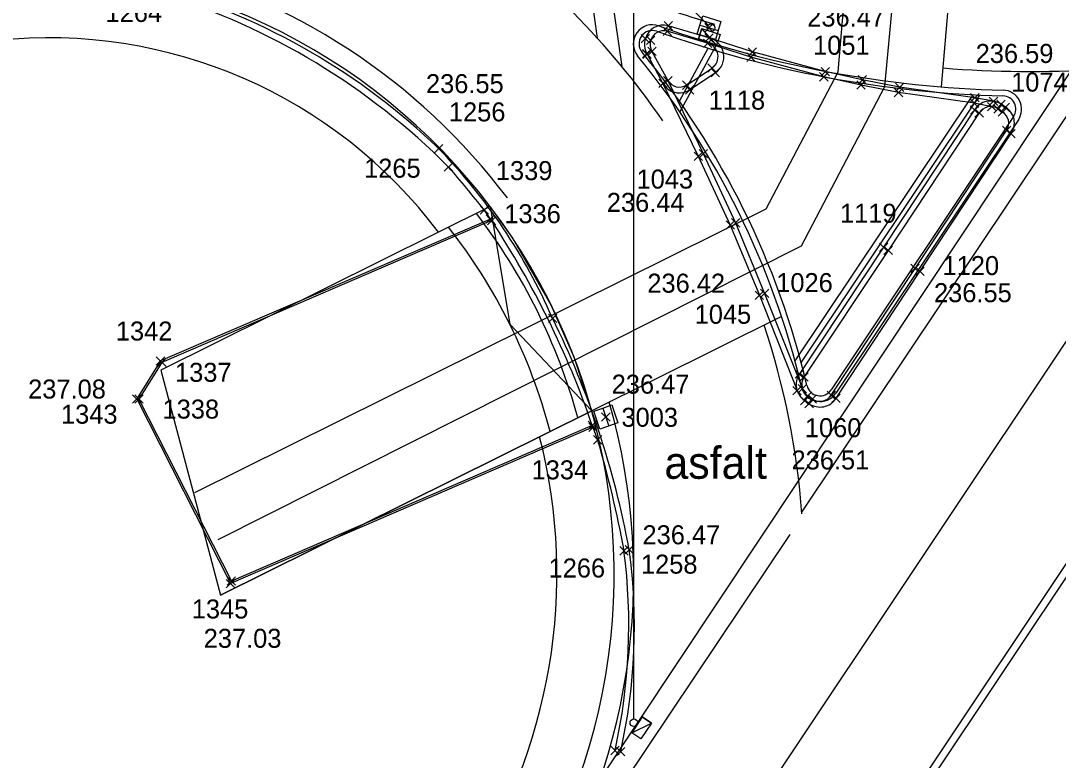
# Model space of a CAD drawing. Extents: x -264205 to -263615, y -1242401 to -1242031.
# Drawn here: x -263835.79 to -263808.5, y -1242333.91 to -1242314.46 of the extents above; entities that cross this region are included whole.
import ezdxf

# ---------------------------------------------------------------- set-up
doc = ezdxf.new("R2010")
doc.units = 0
for name, color, linetype in [('BODY_SYMBOL A CISLO_2-1', 7, 'Continuous'), ('BODY_VYSKA_2-1', 7, 'Continuous'), ('KOORDINACNA_SITUACIA_DSP', 7, 'Continuous'), ('POPIS', 7, 'Continuous'), ('PROJEKT_DRS_TDZ_VODOROVNE', 7, 'Continuous'), ('SO_20-1_OBRUBNIKY_DOLNA_HRANA', 7, 'Continuous'), ('SO_20-1_OBRUBNIKY_HORNA_HRANA', 7, 'Continuous'), ('SO_20-1_UV', 7, 'Continuous')]:
    doc.layers.add(name, color=color, linetype=linetype)

msp = doc.modelspace()

# ---------------------------------------------------------------- linework, layer by layer
at = {"layer": 'BODY_SYMBOL A CISLO_2-1'}
for p, q in [((-263818.899, -1242314.846), (-263818.678, -1242314.626)), ((-263818.678, -1242314.846), (-263818.899, -1242314.626)), ((-263818.872, -1242314.704), (-263818.65, -1242314.484)), ((-263818.65, -1242314.704), (-263818.872, -1242314.484)), ((-263817.799, -1242314.757), (-263817.578, -1242314.535)), ((-263817.578, -1242314.757), (-263817.799, -1242314.535)), ((-263819.474, -1242315.039), (-263819.253, -1242314.819)), ((-263819.253, -1242315.039), (-263819.474, -1242314.819)), ((-263819.335, -1242315.086), (-263819.114, -1242314.865)), ((-263819.114, -1242315.086), (-263819.335, -1242314.865)), ((-263817.801, -1242315.024), (-263817.579, -1242314.802)), ((-263817.579, -1242315.024), (-263817.801, -1242314.802)), ((-263819.302, -1242315.377), (-263819.081, -1242315.157)), ((-263819.081, -1242315.377), (-263819.302, -1242315.157)), ((-263817.838, -1242315.161), (-263817.617, -1242314.941)), ((-263817.617, -1242315.161), (-263817.838, -1242314.941)), ((-263816.658, -1242315.39), (-263816.437, -1242315.17)), ((-263816.437, -1242315.39), (-263816.658, -1242315.17)), ((-263819.44, -1242315.434), (-263819.219, -1242315.214)), ((-263819.219, -1242315.434), (-263819.44, -1242315.214)), ((-263819.43, -1242315.451), (-263819.209, -1242315.231)), ((-263819.209, -1242315.451), (-263819.43, -1242315.231)), ((-263816.696, -1242315.529), (-263816.475, -1242315.308)), ((-263816.475, -1242315.529), (-263816.696, -1242315.308)), ((-263817.719, -1242315.815), (-263817.497, -1242315.593)), ((-263817.497, -1242315.815), (-263817.719, -1242315.593)), ((-263817.636, -1242315.938), (-263817.415, -1242315.718)), ((-263817.415, -1242315.938), (-263817.636, -1242315.718)), ((-263814.743, -1242315.909), (-263814.522, -1242315.688)), ((-263814.522, -1242315.909), (-263814.743, -1242315.688)), ((-263819.013, -1242316.218), (-263818.791, -1242315.998)), ((-263818.791, -1242316.218), (-263819.013, -1242315.998)), ((-263818.883, -1242316.146), (-263818.662, -1242315.924)), ((-263818.662, -1242316.146), (-263818.883, -1242315.924)), ((-263814.78, -1242316.046), (-263814.558, -1242315.825)), ((-263814.558, -1242316.046), (-263814.78, -1242315.825)), ((-263813.77, -1242316.126), (-263813.549, -1242315.904)), ((-263813.549, -1242316.126), (-263813.77, -1242315.904)), ((-263818.391, -1242316.265), (-263818.17, -1242316.043)), ((-263818.17, -1242316.265), (-263818.391, -1242316.043)), ((-263818.312, -1242316.389), (-263818.09, -1242316.167)), ((-263818.09, -1242316.389), (-263818.312, -1242316.167)), ((-263813.8, -1242316.262), (-263813.579, -1242316.042)), ((-263813.579, -1242316.262), (-263813.8, -1242316.042)), ((-263812.815, -1242316.46), (-263812.594, -1242316.238)), ((-263812.594, -1242316.46), (-263812.815, -1242316.238)), ((-263812.788, -1242316.32), (-263812.567, -1242316.1)), ((-263812.567, -1242316.32), (-263812.788, -1242316.1)), ((-263810.819, -1242316.738), (-263810.598, -1242316.518)), ((-263810.598, -1242316.738), (-263810.819, -1242316.518)), ((-263810.808, -1242316.596), (-263810.587, -1242316.374)), ((-263810.587, -1242316.596), (-263810.808, -1242316.374)), ((-263810.317, -1242316.688), (-263810.095, -1242316.468)), ((-263810.095, -1242316.688), (-263810.317, -1242316.468)), ((-263810.815, -1242316.917), (-263810.594, -1242316.697)), ((-263810.594, -1242316.917), (-263810.815, -1242316.697)), ((-263810.694, -1242316.997), (-263810.473, -1242316.775)), ((-263810.473, -1242316.997), (-263810.694, -1242316.775)), ((-263810.361, -1242316.833), (-263810.139, -1242316.612)), ((-263810.139, -1242316.833), (-263810.361, -1242316.612)), ((-263810.199, -1242316.89), (-263809.978, -1242316.67)), ((-263809.978, -1242316.89), (-263810.199, -1242316.67)), ((-263810.118, -1242316.768), (-263809.897, -1242316.546)), ((-263809.897, -1242316.768), (-263810.118, -1242316.546)), ((-263810.08, -1242316.97), (-263809.859, -1242316.748)), ((-263809.859, -1242316.97), (-263810.08, -1242316.748)), ((-263810.003, -1242316.846), (-263809.781, -1242316.624)), ((-263809.781, -1242316.846), (-263810.003, -1242316.624)), ((-263809.971, -1242317.454), (-263809.75, -1242317.232)), ((-263809.75, -1242317.454), (-263809.971, -1242317.232)), ((-263809.854, -1242317.539), (-263809.633, -1242317.318)), ((-263809.633, -1242317.539), (-263809.854, -1242317.318)), ((-263824.91, -1242317.936), (-263824.688, -1242317.715)), ((-263824.688, -1242317.936), (-263824.91, -1242317.715)), ((-263817.951, -1242318.066), (-263817.73, -1242317.845)), ((-263817.73, -1242318.066), (-263817.951, -1242317.845)), ((-263818.084, -1242318.134), (-263817.862, -1242317.914)), ((-263817.862, -1242318.134), (-263818.084, -1242317.914)), ((-263824.653, -1242318.418), (-263824.432, -1242318.198)), ((-263824.432, -1242318.418), (-263824.653, -1242318.198)), ((-263823.712, -1242319.546), (-263823.491, -1242319.326)), ((-263823.491, -1242319.546), (-263823.712, -1242319.326)), ((-263823.549, -1242319.786), (-263823.328, -1242319.566)), ((-263823.328, -1242319.786), (-263823.549, -1242319.566)), ((-263823.52, -1242319.829), (-263823.299, -1242319.607)), ((-263823.299, -1242319.829), (-263823.52, -1242319.607)), ((-263817.24, -1242319.944), (-263817.019, -1242319.722)), ((-263817.019, -1242319.944), (-263817.24, -1242319.722)), ((-263817.101, -1242319.887), (-263816.88, -1242319.666)), ((-263816.88, -1242319.887), (-263817.101, -1242319.666)), ((-263813.208, -1242320.529), (-263812.986, -1242320.309)), ((-263812.986, -1242320.529), (-263813.208, -1242320.309)), ((-263813.089, -1242320.612), (-263812.867, -1242320.39)), ((-263812.867, -1242320.612), (-263813.089, -1242320.39)), ((-263812.378, -1242321.086), (-263812.157, -1242320.866)), ((-263812.157, -1242321.086), (-263812.378, -1242320.866)), ((-263812.253, -1242321.164), (-263812.031, -1242320.943)), ((-263812.031, -1242321.164), (-263812.253, -1242320.943)), ((-263816.474, -1242321.792), (-263816.253, -1242321.572)), ((-263816.253, -1242321.792), (-263816.474, -1242321.572)), ((-263816.338, -1242321.742), (-263816.117, -1242321.522)), ((-263816.117, -1242321.742), (-263816.338, -1242321.522)), ((-263821.916, -1242322.396), (-263821.695, -1242322.174)), ((-263821.695, -1242322.396), (-263821.916, -1242322.174)), ((-263832.228, -1242323.519), (-263832.007, -1242323.299)), ((-263832.007, -1242323.519), (-263832.228, -1242323.299)), ((-263832.193, -1242323.559), (-263831.972, -1242323.339)), ((-263831.972, -1242323.559), (-263832.193, -1242323.339)), ((-263815.422, -1242323.86), (-263815.202, -1242323.64)), ((-263815.202, -1242323.86), (-263815.422, -1242323.64)), ((-263815.302, -1242323.941), (-263815.081, -1242323.721)), ((-263815.081, -1242323.941), (-263815.302, -1242323.721)), ((-263815.482, -1242324.301), (-263815.261, -1242324.079)), ((-263815.261, -1242324.301), (-263815.482, -1242324.079)), ((-263815.344, -1242324.245), (-263815.122, -1242324.025)), ((-263815.122, -1242324.245), (-263815.344, -1242324.025)), ((-263832.855, -1242324.519), (-263832.633, -1242324.299)), ((-263832.633, -1242324.519), (-263832.855, -1242324.299)), ((-263832.797, -1242324.522), (-263832.576, -1242324.301)), ((-263832.576, -1242324.522), (-263832.797, -1242324.301)), ((-263815.285, -1242324.561), (-263815.063, -1242324.34)), ((-263815.063, -1242324.561), (-263815.285, -1242324.34)), ((-263815.202, -1242324.438), (-263814.981, -1242324.217)), ((-263814.981, -1242324.438), (-263815.202, -1242324.217)), ((-263815.165, -1242324.643), (-263814.943, -1242324.421)), ((-263814.943, -1242324.643), (-263815.165, -1242324.421)), ((-263815.084, -1242324.519), (-263814.862, -1242324.299)), ((-263814.862, -1242324.519), (-263815.084, -1242324.299)), ((-263814.584, -1242324.421), (-263814.362, -1242324.2)), ((-263814.362, -1242324.421), (-263814.584, -1242324.2)), ((-263814.458, -1242324.502), (-263814.236, -1242324.281)), ((-263814.236, -1242324.502), (-263814.458, -1242324.281)), ((-263820.87, -1242325.215), (-263820.649, -1242324.995)), ((-263820.649, -1242325.215), (-263820.87, -1242324.995)), ((-263820.514, -1242324.995), (-263820.293, -1242324.774)), ((-263820.293, -1242324.995), (-263820.514, -1242324.774)), ((-263820.853, -1242325.262), (-263820.632, -1242325.042)), ((-263820.632, -1242325.262), (-263820.853, -1242325.042)), ((-263820.73, -1242325.596), (-263820.508, -1242325.374)), ((-263820.508, -1242325.596), (-263820.73, -1242325.374)), ((-263819.899, -1242328.484), (-263819.677, -1242328.262)), ((-263819.677, -1242328.484), (-263819.899, -1242328.262)), ((-263820.036, -1242328.514), (-263819.815, -1242328.292)), ((-263819.815, -1242328.514), (-263820.036, -1242328.292)), ((-263830.365, -1242329.309), (-263830.144, -1242329.088)), ((-263830.144, -1242329.309), (-263830.365, -1242329.088)), ((-263830.388, -1242329.373), (-263830.166, -1242329.153)), ((-263830.166, -1242329.373), (-263830.388, -1242329.153)), ((-263820.272, -1242333.765), (-263820.051, -1242333.543)), ((-263820.051, -1242333.765), (-263820.272, -1242333.543)), ((-263820.123, -1242333.796), (-263819.902, -1242333.576)), ((-263819.902, -1242333.796), (-263820.123, -1242333.576))]:
    msp.add_line(p, q, dxfattribs=at)
at = {"layer": 'KOORDINACNA_SITUACIA_DSP'}
for p, q in [((-263822.88, -1242337.914), (-263734.49, -1242204.937)), ((-263819.667, -1242332.824), (-263819.667, -1242304.147)), ((-263817.708, -1242314.574), (-263819.667, -1242312.615)), ((-263817.966, -1242314.94), (-263817.874, -1242314.665)), ((-263817.874, -1242314.665), (-263817.966, -1242314.94)), ((-263817.874, -1242314.665), (-263817.4, -1242314.824)), ((-263817.492, -1242315.099), (-263817.874, -1242314.665)), ((-263817.492, -1242315.099), (-263817.874, -1242314.665)), ((-263817.4, -1242314.824), (-263817.492, -1242315.099)), ((-263818.453, -1242316.866), (-263817.491, -1242315.093)), ((-263817.492, -1242315.099), (-263817.966, -1242314.94)), ((-263817.966, -1242314.94), (-263817.492, -1242315.099)), ((-263818.469, -1242316.58), (-263817.711, -1242315.183)), ((-263810.751, -1242316.405), (-263815.43, -1242323.41)), ((-263810.576, -1242316.414), (-263815.268, -1242323.437)), ((-263809.676, -1242316.98), (-263814.48, -1242324.171)), ((-263809.551, -1242317.064), (-263814.356, -1242324.254)), ((-263823.444, -1242319.346), (-263832.112, -1242323.652)), ((-263813.542, -1242320.69), (-263813.542, -1242320.69)), ((-263813.542, -1242320.69), (-263813.542, -1242320.69)), ((-263832.112, -1242323.652), (-263830.544, -1242329.573)), ((-263820.775, -1242324.719), (-263830.544, -1242329.573)), ((-263819.723, -1242333.187), (-263819.444, -1242332.772)), ((-263819.444, -1242332.772), (-263819.203, -1242332.933)), ((-263819.723, -1242333.187), (-263819.203, -1242332.933)), ((-263819.482, -1242333.349), (-263819.723, -1242333.187)), ((-263819.203, -1242332.933), (-263819.482, -1242333.349))]:
    msp.add_line(p, q, dxfattribs=at)
for points in [[(-263832.112, -1242323.652), (-263830.544, -1242329.573), (-263820.775, -1242324.719), (-263821.24, -1242323.31), (-263821.84, -1242321.938), (-263822.869, -1242320.154), (-263823.444, -1242319.346), (-263832.112, -1242323.652)], [(-263823.444, -1242319.346), (-263822.93, -1242322.44), (-263820.775, -1242324.719)]]:
    msp.add_lwpolyline(points, dxfattribs=at)
msp.add_lwpolyline([(-263819.723, -1242333.187), (-263819.203, -1242332.933), (-263819.444, -1242332.772)], close=True, dxfattribs=at)
for centre in [(-263817.637, -1242314.644), (-263819.667, -1242332.924)]:
    msp.add_circle(centre, 0.1, dxfattribs=at)
for centre, radius, start, end in [((-263836.184, -1242329.025), 16, 326.2529, 76.9695), ((-263819.181, -1242315.066), 0.5, 70.2828, 219.3857), ((-263809.228, -1242287.295), 29, 250.2828, 268.5641), ((-263819.181, -1242315.066), 0.35, 70.2828, 219.3857), ((-263809.228, -1242287.295), 29.15, 250.2828, 268.5641), ((-263835.045, -1242327.715), 12.805, 36.9205, 96.0874), ((-263836.184, -1242329.025), 21.5, 13.267, 39.3857), ((-263836.184, -1242329.025), 21.65, 13.267, 39.3857), ((-263809.967, -1242316.786), 0.35, 326.2529, 88.5641), ((-263809.967, -1242316.786), 0.5, 326.2529, 88.5641), ((-263836.184, -1242329.025), 15.6, 15.3332, 37.5082), ((-263836.184, -1242329.025), 14.8, 14.7256, 38.1157), ((-263836.184, -1242329.025), 21.65, 13.267, 14.9596), ((-263814.771, -1242323.977), 0.5, 193.267, 326.2529), ((-263814.771, -1242323.977), 0.35, 193.267, 326.2529), ((-263836.228, -1242329.021), 14.539, 326.3344, 14.4166)]:
    msp.add_arc(centre, radius, start, end, dxfattribs=at)
at = {"layer": 'PROJEKT_DRS_TDZ_VODOROVNE'}
for p, q in [((-263824.083, -1242346.553), (-263789.385, -1242294.564)), ((-263811.571, -1242316.2), (-263811.101, -1242310.72)), ((-263820.866, -1242313.273), (-263820.628, -1242314.918)), ((-263820.29, -1242313.528), (-263819.981, -1242315.667)), ((-263815.248, -1242327.389), (-263807.46, -1242315.74)), ((-263815.783, -1242322.239), (-263820.775, -1242324.719)), ((-263821.435, -1242348.441), (-263806.091, -1242325.442)), ((-263821.286, -1242348.578), (-263805.925, -1242325.553)), ((-263822.425, -1242338.218), (-263815.553, -1242327.973))]:
    msp.add_line(p, q, dxfattribs=at)
for points in [[(-263831.211, -1242326.873), (-263816.19, -1242319.41), (-263814.291, -1242315.804), (-263813.06, -1242301.353), (-263812.968, -1242299.181), (-263802.618, -1242291.831), (-263801.478, -1242290.893), (-263800.257, -1242289.755), (-263799.049, -1242288.464), (-263798.027, -1242287.218), (-263749.798, -1242216.488), (-263742.736, -1242211.145)], [(-263830.6, -1242328.105), (-263815.26, -1242320.378), (-263813.062, -1242316.188), (-263811.682, -1242301.389), (-263811.608, -1242300.055), (-263801.705, -1242293.023), (-263800.489, -1242292.021), (-263799.197, -1242290.817), (-263797.92, -1242289.454), (-263796.825, -1242288.118), (-263748.697, -1242217.536), (-263741.831, -1242212.341)]]:
    msp.add_lwpolyline(points, dxfattribs=at)
for centre, radius, start, end in [((-263836.184, -1242329.025), 21, 34.6339, 54.8237), ((-263836.225, -1242329.073), 16.555, 36.9462, 76.8694), ((-263809.228, -1242287.295), 28.5, 248.0197, 253.0257), ((-263809.228, -1242287.295), 28.5, 265.3711, 273.5562), ((-263836.184, -1242329.025), 21, 4.3491, 18.2075), ((-263836.225, -1242329.073), 16.555, 326.4668, 16.0654)]:
    msp.add_arc(centre, radius, start, end, dxfattribs=at)
at = {"layer": 'SO_20-1_OBRUBNIKY_DOLNA_HRANA'}
msp.add_line((-263815.174, -1242324.45), (-263815.054, -1242324.532), dxfattribs=at)
for points in [[(-263817.69, -1242314.913), (-263818.761, -1242314.594)], [(-263810.206, -1242316.578), (-263810.698, -1242316.485), (-263812.677, -1242316.21), (-263813.66, -1242316.015), (-263814.633, -1242315.798), (-263816.547, -1242315.28), (-263817.69, -1242314.913)], [(-263819.319, -1242315.341), (-263818.902, -1242316.108)], [(-263818.201, -1242316.278), (-263817.525, -1242315.828)], [(-263818.902, -1242316.108), (-263817.973, -1242318.024), (-263817.129, -1242319.833), (-263816.363, -1242321.682), (-263815.372, -1242324.19)], [(-263810.704, -1242316.807), (-263813.097, -1242320.419), (-263815.312, -1242323.75)], [(-263809.892, -1242316.735), (-263810.008, -1242316.657)], [(-263814.347, -1242324.391), (-263812.142, -1242321.053), (-263809.743, -1242317.428)]]:
    msp.add_lwpolyline(points, dxfattribs=at)
for centre, major_axis, ratio, start_param, end_param in [((-263836.917, -1242330.389), (-12.568, 12.147), 0.998664, 4.713467, 5.197044), ((-263818.893, -1242315.066), (0.148, -0.467), 0.999867, 2.562738, 4.12235), ((-263818.868, -1242315.085), (0.045, -0.517), 0.999806, 4.320521, 5.104257), ((-263817.803, -1242315.406), (0.39, 0.323), 0.999315, 4.602925, 6.93754), ((-263818.47, -1242315.857), (-0.486, 0.118), 0.999915, 0.764319, 2.377274), ((-263810.284, -1242317.065), (-0.259, 0.419), 0.999812, 5.134851, 6.750861), ((-263810.141, -1242317.151), (0.065, 0.481), 0.999991, 4.238012, 5.877529), ((-263835.299, -1242328.082), (-9.097, 11.695), 0.990566, 4.45941, 4.823964), ((-263842.758, -1242332.613), (-5.115, 22.811), 0.999168, 4.674361, 4.949582), ((-263814.893, -1242324.031), (-0.282, 0.418), 0.999941, 0.386314, 1.958336), ((-263814.769, -1242324.118), (0.274, -0.422), 0.999972, 5.104611, 6.703858), ((-263834.807, -1242330.397), (-3.889, 14.649), 0.999894, 4.234216, 4.586906)]:
    msp.add_ellipse(centre, major_axis=major_axis, ratio=ratio, start_param=start_param, end_param=end_param, dxfattribs=at)
at = {"layer": 'SO_20-1_OBRUBNIKY_HORNA_HRANA'}
for p, q in [((-263823.41, -1242319.718), (-263823.601, -1242319.436)), ((-263823.438, -1242319.676), (-263823.41, -1242319.718)), ((-263832.744, -1242324.409), (-263830.277, -1242329.263)), ((-263832.687, -1242324.411), (-263830.254, -1242329.198)), ((-263815.091, -1242324.327), (-263814.973, -1242324.409)), ((-263820.742, -1242325.152), (-263830.277, -1242329.263)), ((-263820.759, -1242325.105), (-263830.254, -1242329.198)), ((-263820.759, -1242325.105), (-263820.619, -1242325.485)), ((-263820.742, -1242325.152), (-263820.759, -1242325.105))]:
    msp.add_line(p, q, dxfattribs=at)
for points in [[(-263817.727, -1242315.051), (-263818.789, -1242314.736)], [(-263810.25, -1242316.722), (-263810.709, -1242316.628), (-263812.704, -1242316.349), (-263813.689, -1242316.152), (-263814.669, -1242315.935), (-263816.585, -1242315.418), (-263817.727, -1242315.051)], [(-263819.192, -1242315.267), (-263818.773, -1242316.035)], [(-263818.28, -1242316.154), (-263817.608, -1242315.704)], [(-263818.773, -1242316.035), (-263817.84, -1242317.955), (-263816.991, -1242319.776), (-263816.227, -1242321.632), (-263815.233, -1242324.135)], [(-263809.97, -1242316.859), (-263810.089, -1242316.78)], [(-263810.584, -1242316.886), (-263812.978, -1242320.501), (-263815.192, -1242323.831)], [(-263814.473, -1242324.31), (-263812.268, -1242320.976), (-263809.861, -1242317.343)], [(-263823.438, -1242319.676), (-263832.117, -1242323.409), (-263832.744, -1242324.409)], [(-263823.41, -1242319.718), (-263832.083, -1242323.449), (-263832.687, -1242324.411)]]:
    msp.add_lwpolyline(points, dxfattribs=at)
for centre, major_axis, ratio, start_param, end_param in [((-263837.329, -1242331.009), (-13.346, 12.171), 0.997839, 4.663107, 5.155176), ((-263818.881, -1242315.086), (0.067, -0.355), 0.999729, 2.699114, 4.216297), ((-263818.883, -1242315.084), (-0.063, -0.354), 0.999357, 4.579753, 5.422246), ((-263817.816, -1242315.405), (0.31, 0.192), 0.999422, 4.763927, 7.052938), ((-263818.467, -1242315.846), (0.335, -0.13), 0.999891, 4.064262, 5.628365), ((-263810.285, -1242317.071), (-0.288, 0.202), 0.999767, 4.729783, 6.338871), ((-263810.156, -1242317.155), (-0.077, 0.341), 0.999809, 3.924248, 5.50053), ((-263849.035, -1242339.606), (-22.317, 24.858), 0.971582, 4.653005, 4.696983), ((-263843.342, -1242332.884), (-0.791, 23.885), 0.999409, 5.010846, 5.262764), ((-263814.885, -1242324.027), (-0.325, 0.164), 0.999886, 6.182815, 7.71937), ((-263814.772, -1242324.114), (0.357, 0.013), 0.998096, 4.078566, 5.665653), ((-263846.347, -1242333.123), (-8.061, 25.7), 0.996418, 4.585653, 4.697064), ((-263834.962, -1242330.362), (1.128, 15.134), 0.999102, 4.568049, 4.916141)]:
    msp.add_ellipse(centre, major_axis=major_axis, ratio=ratio, start_param=start_param, end_param=end_param, dxfattribs=at)
at = {"layer": 'SO_20-1_UV'}
for p, q in [((-263817.688, -1242314.646), (-263817.688, -1242314.646)), ((-263820.404, -1242324.884), (-263820.404, -1242324.884))]:
    msp.add_line(p, q, dxfattribs=at)
for points in [[(-263817.927, -1242314.574), (-263817.855, -1242314.335), (-263817.377, -1242314.479), (-263817.521, -1242314.957), (-263817.999, -1242314.813), (-263817.927, -1242314.574), (-263817.449, -1242314.718)], [(-263820.486, -1242324.648), (-263820.25, -1242324.566), (-263820.086, -1242325.038), (-263820.558, -1242325.202), (-263820.722, -1242324.73), (-263820.486, -1242324.648), (-263820.322, -1242325.12)]]:
    msp.add_lwpolyline(points, dxfattribs=at)

# ---------------------------------------------------------------- texts
at = {"layer": 'BODY_SYMBOL A CISLO_2-1'}
for s, p in [('1264', (-263833.564, -1242314.492)), ('1051', (-263814.951, -1242315.354)), ('1074', (-263809.742, -1242316.324)), ('1118', (-263817.7, -1242316.798)), ('1256', (-263824.532, -1242317.108)), ('1265', (-263826.762, -1242318.589)), ('1339', (-263823.296, -1242318.652)), ('1043', (-263819.595, -1242318.875)), ('1119', (-263814.244, -1242319.774)), ('1336', (-263823.075, -1242319.786)), ('1120', (-263811.546, -1242321.15)), ('1026', (-263815.921, -1242321.598)), ('1045', (-263818.067, -1242322.431)), ('1342', (-263833.292, -1242322.872)), ('1337', (-263831.736, -1242323.958)), ('1338', (-263832.064, -1242324.925)), ('1343', (-263834.735, -1242325.059)), ('3003', (-263819.993, -1242325.14)), ('1060', (-263815.168, -1242325.414)), ('1334', (-263822.357, -1242326.523)), ('1258', (-263819.48, -1242329.003)), ('1266', (-263821.91, -1242329.105)), ('1345', (-263831.295, -1242330.183))]:
    msp.add_text(s, height=0.5, dxfattribs=at).set_placement(p)
at = {"layer": 'BODY_VYSKA_2-1'}
for s, p in [('236.47', (-263815.105, -1242314.614)), ('236.59', (-263810.675, -1242315.571)), ('236.55', (-263825.135, -1242316.365)), ('236.44', (-263820.378, -1242319.488)), ('236.42', (-263819.312, -1242321.613)), ('236.55', (-263811.771, -1242321.863)), ('237.08', (-263835.6, -1242324.397)), ('236.47', (-263820.25, -1242324.269)), ('236.51', (-263815.518, -1242326.263)), ('236.47', (-263819.439, -1242328.231)), ('237.03', (-263830.982, -1242330.954))]:
    msp.add_text(s, height=0.5, dxfattribs=at).set_placement(p)
at = {"layer": 'POPIS'}
msp.add_text('asfalt', height=0.8438, dxfattribs=at).set_placement((-263818.863, -1242326.508))

doc.saveas('drawing.dxf')
